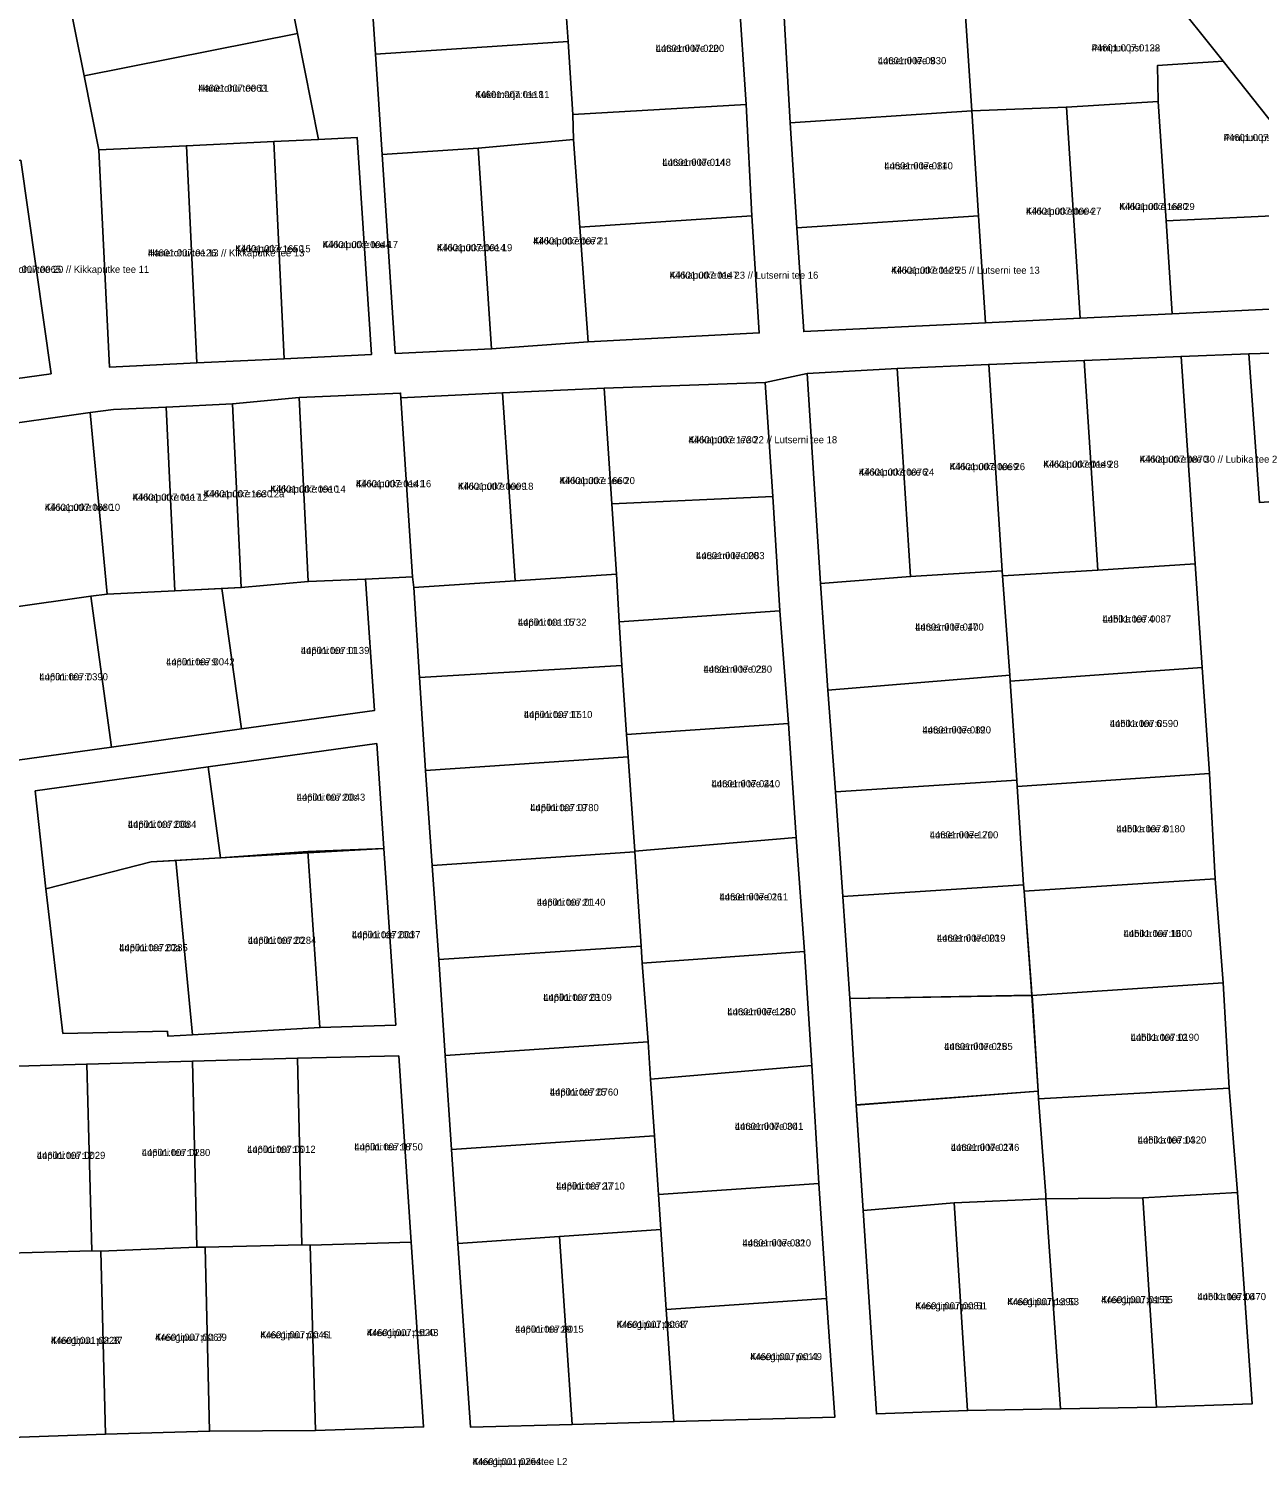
# Model space of a CAD drawing. Extents: x 551843 to 558501, y 6589003 to 6595718.
# Drawn here: x 554118.2 to 554378.5, y 6593051.3 to 6593355.7 of the extents above; entities that cross this region are included whole.
import ezdxf

# ---------------------------------------------------------------- set-up
doc = ezdxf.new("R2010")
doc.units = 0
for name, color, linetype in [('L_AADRESS', 7, 'Continuous'), ('PIIR', 7, 'Continuous'), ('TUNNUS', 7, 'Continuous')]:
    doc.layers.add(name, color=color, linetype=linetype)

msp = doc.modelspace()

# ---------------------------------------------------------------- linework, layer by layer
at = {"layer": 'PIIR'}
for points in [[(554175.06, 6593354.75), (554129.94, 6593345.76), (554126.15, 6593364.79), (554171.26, 6593373.78)], [(554191.59, 6593350.39), (554190.19, 6593371.62), (554230.91, 6593374.28), (554231.71, 6593362.02), (554232.3, 6593353.05)], [(554232.3, 6593353.05), (554231.71, 6593362.02), (554268.35, 6593364.09), (554269.98, 6593339.69), (554233.34, 6593337.62)], [(554316.4, 6593361.22), (554355.96, 6593363.33), (554359.29, 6593363.51), (554370.87, 6593348.86), (554357.01, 6593347.99), (554357.18, 6593340.35), (554337.73, 6593339.18), (554317.72, 6593338.39), (554316.26, 6593360.62)], [(554316.26, 6593360.62), (554317.72, 6593338.39), (554279.27, 6593335.87), (554278, 6593358.18)], [(554175.06, 6593354.75), (554179.53, 6593332.32), (554170.03, 6593331.87), (554151.55, 6593330.99), (554133.07, 6593330.1), (554129.94, 6593345.76)], [(554192.98, 6593329.15), (554191.59, 6593350.39), (554232.3, 6593353.05), (554233.34, 6593337.62), (554233.47, 6593332.32), (554213.29, 6593330.48)], [(554358.84, 6593315.1), (554357.18, 6593340.35), (554357.01, 6593347.99), (554370.87, 6593348.86), (554396.28, 6593316.9)], [(554269.98, 6593339.69), (554271.15, 6593316.19), (554234.81, 6593313.78), (554233.47, 6593332.32), (554233.34, 6593337.62)], [(554340.65, 6593294.5), (554320.59, 6593293.53), (554319.14, 6593316.15), (554317.72, 6593338.39), (554337.73, 6593339.18)], [(554357.18, 6593340.35), (554358.84, 6593315.1), (554360.13, 6593295.44), (554340.65, 6593294.5), (554337.73, 6593339.18)], [(554317.72, 6593338.39), (554319.14, 6593316.15), (554280.73, 6593313.59), (554279.27, 6593335.87)], [(554135.27, 6593284.15), (554133.07, 6593330.1), (554151.55, 6593330.99), (554153.75, 6593285.04)], [(554170.03, 6593331.87), (554172.23, 6593285.91), (554153.75, 6593285.04), (554151.55, 6593330.99)], [(554179.53, 6593332.32), (554187.71, 6593332.72), (554190.72, 6593286.8), (554172.23, 6593285.91), (554170.03, 6593331.87)], [(554213.29, 6593330.48), (554216.14, 6593288.01), (554195.74, 6593287.03), (554192.98, 6593329.15)], [(554213.29, 6593330.48), (554233.47, 6593332.32), (554234.81, 6593313.78), (554236.56, 6593289.51), (554216.14, 6593288.01)], [(554116.53, 6593327.97), (554122.93, 6593282.74), (554104.61, 6593280.19), (554098.21, 6593325.42)], [(554271.15, 6593316.19), (554272.75, 6593291.4), (554236.56, 6593289.51), (554234.81, 6593313.78)], [(554282.17, 6593291.65), (554280.73, 6593313.59), (554319.14, 6593316.15), (554320.59, 6593293.53)], [(554358.84, 6593315.1), (554396.28, 6593316.9), (554411.57, 6593297.9), (554360.13, 6593295.44)], [(554405.33, 6593287.82), (554407.5, 6593257.53), (554378.58, 6593255.52), (554376.33, 6593286.93)], [(554301.93, 6593283.84), (554321.32, 6593284.7), (554324.15, 6593241.06), (554304.78, 6593239.83)], [(554324.22, 6593239.97), (554324.15, 6593241.06), (554321.32, 6593284.7), (554341.49, 6593285.56), (554344.39, 6593241.21)], [(554341.49, 6593285.56), (554362.01, 6593286.41), (554364.98, 6593242.53), (554344.39, 6593241.21)], [(554301.93, 6593283.84), (554304.78, 6593239.83), (554285.73, 6593238.37), (554282.86, 6593282.78)], [(554196.86, 6593278.64), (554196.92, 6593277.68), (554199.41, 6593239.75), (554189.45, 6593239.3), (554177.34, 6593238.75), (554175.42, 6593277.75)], [(554199.69, 6593237.49), (554199.41, 6593239.75), (554196.92, 6593277.68), (554218.47, 6593278.69), (554221.13, 6593238.92)], [(554221.13, 6593238.92), (554218.47, 6593278.69), (554239.95, 6593279.66), (554241.55, 6593255.18), (554242.52, 6593240.34)], [(554239.95, 6593279.66), (554274.01, 6593280.87), (554275.63, 6593256.79), (554241.55, 6593255.18)], [(554147.25, 6593275.7), (554149.14, 6593236.81), (554134.82, 6593236.12), (554131.2, 6593274.53), (554136.13, 6593275.17)], [(554161.29, 6593276.37), (554163.18, 6593237.48), (554149.14, 6593236.81), (554147.25, 6593275.7)], [(554175.42, 6593277.75), (554177.34, 6593238.75), (554163.18, 6593237.48), (554161.29, 6593276.37)], [(554131.2, 6593274.53), (554134.82, 6593236.12), (554131.32, 6593235.64), (554114.03, 6593233.23), (554108.36, 6593271.31)], [(554277.11, 6593232.55), (554243.14, 6593230.23), (554242.52, 6593240.34), (554241.55, 6593255.18), (554275.63, 6593256.79)], [(554344.39, 6593241.21), (554364.98, 6593242.53), (554366.45, 6593220.55), (554325.84, 6593217.67), (554325.77, 6593218.95), (554324.22, 6593239.97)], [(554163.2, 6593207.57), (554159.07, 6593237.28), (554163.18, 6593237.48), (554177.34, 6593238.75), (554189.45, 6593239.3), (554191.37, 6593211.49)], [(554199.69, 6593237.49), (554221.13, 6593238.92), (554242.52, 6593240.34), (554243.14, 6593230.23), (554243.69, 6593220.98), (554200.91, 6593218.48)], [(554285.73, 6593238.37), (554304.78, 6593239.83), (554324.15, 6593241.06), (554324.22, 6593239.97), (554325.77, 6593218.95), (554287.28, 6593215.75)], [(554105.17, 6593232), (554114.03, 6593233.23), (554131.32, 6593235.64), (554135.74, 6593203.74), (554109.59, 6593200.1)], [(554134.82, 6593236.12), (554149.14, 6593236.81), (554159.07, 6593237.28), (554163.2, 6593207.57), (554135.74, 6593203.74), (554131.32, 6593235.64)], [(554277.11, 6593232.55), (554278.95, 6593208.76), (554244.66, 6593206.42), (554243.69, 6593220.98), (554243.14, 6593230.23)], [(554202.18, 6593198.78), (554200.91, 6593218.48), (554243.69, 6593220.98), (554244.66, 6593206.42), (554244.99, 6593201.65)], [(554366.45, 6593220.55), (554368.01, 6593198.12), (554327.34, 6593195.43), (554327.26, 6593196.73), (554325.84, 6593217.67)], [(554287.28, 6593215.75), (554325.77, 6593218.95), (554325.84, 6593217.67), (554327.26, 6593196.73), (554288.9, 6593194.28)], [(554278.95, 6593208.76), (554280.59, 6593184.61), (554246.44, 6593181.71), (554244.99, 6593201.65), (554244.66, 6593206.42)], [(554156.17, 6593199.53), (554119.59, 6593194.45), (554121.83, 6593173.77), (554125.45, 6593143.15), (554147.56, 6593143.6), (554147.66, 6593142.55), (554152.85, 6593142.85), (554179.81, 6593144.38), (554195.86, 6593144.9), (554193.33, 6593182.25), (554191.83, 6593204.49)], [(554191.83, 6593204.49), (554193.33, 6593182.25), (554177.3, 6593181.34), (554158.79, 6593180.27), (554156.17, 6593199.53)], [(554121.83, 6593173.77), (554119.59, 6593194.45), (554156.17, 6593199.53), (554158.79, 6593180.27), (554144.12, 6593179.43)], [(554202.18, 6593198.78), (554244.99, 6593201.65), (554246.44, 6593181.71), (554246.45, 6593181.55), (554203.57, 6593178.71)], [(554327.26, 6593196.73), (554327.34, 6593195.43), (554328.66, 6593174.57), (554290.47, 6593172.1), (554288.9, 6593194.28)], [(554368.01, 6593198.12), (554369.24, 6593175.88), (554328.79, 6593173.27), (554328.66, 6593174.57), (554327.34, 6593195.43)], [(554247.98, 6593158), (554247.78, 6593161.58), (554246.45, 6593181.55), (554246.44, 6593181.71), (554280.59, 6593184.61), (554282.36, 6593160.5)], [(554149.3, 6593179.73), (554158.79, 6593180.27), (554177.28, 6593181.62), (554179.81, 6593144.38), (554152.85, 6593142.85)], [(554193.33, 6593182.25), (554195.86, 6593144.9), (554179.81, 6593144.38), (554177.28, 6593181.62)], [(554203.57, 6593178.71), (554246.45, 6593181.55), (554247.78, 6593161.58), (554204.96, 6593158.76)], [(554121.83, 6593173.77), (554144.12, 6593179.43), (554149.3, 6593179.73), (554152.85, 6593142.85), (554147.66, 6593142.55), (554147.56, 6593143.6), (554125.45, 6593143.15)], [(554328.79, 6593173.27), (554369.24, 6593175.88), (554370.87, 6593153.82), (554330.42, 6593151.19), (554330.33, 6593152.65)], [(554328.79, 6593173.27), (554330.42, 6593151.19), (554291.89, 6593150.56), (554290.47, 6593172.1), (554328.66, 6593174.57)], [(554206.33, 6593138.47), (554204.96, 6593158.76), (554247.78, 6593161.58), (554247.98, 6593158), (554249.22, 6593141.38)], [(554282.36, 6593160.5), (554283.88, 6593136.38), (554249.76, 6593133.49), (554249.22, 6593141.38), (554247.98, 6593158)], [(554370.87, 6593153.82), (554372.19, 6593131.53), (554331.83, 6593129.31), (554331.74, 6593130.91), (554330.42, 6593151.19)], [(554291.89, 6593150.54), (554330.48, 6593151.26), (554331.74, 6593130.91), (554293.23, 6593128.04)], [(554206.33, 6593138.47), (554249.22, 6593141.38), (554249.76, 6593133.49), (554250.57, 6593121.5), (554207.67, 6593118.59)], [(554196.48, 6593138.39), (554199.12, 6593098.96), (554177.72, 6593098.34), (554175.96, 6593098.42), (554175.06, 6593137.9)], [(554130.47, 6593136.64), (554131.56, 6593097.15), (554111.31, 6593096.59), (554109.34, 6593096.54), (554108.25, 6593136.03)], [(554152.84, 6593137.24), (554153.74, 6593097.91), (554133.43, 6593097.09), (554131.56, 6593097.15), (554130.47, 6593136.64)], [(554152.84, 6593137.24), (554175.06, 6593137.9), (554175.96, 6593098.42), (554155.52, 6593097.94), (554153.74, 6593097.91)], [(554283.88, 6593136.38), (554285.34, 6593111.42), (554251.42, 6593109.09), (554250.57, 6593121.5), (554249.76, 6593133.49)], [(554293.24, 6593127.98), (554331.74, 6593130.91), (554331.83, 6593129.31), (554333.36, 6593108.94), (554333.41, 6593108.17), (554313.98, 6593107.27), (554294.73, 6593105.67)], [(554372.19, 6593131.53), (554373.91, 6593109.51), (554353.87, 6593108.34), (554333.41, 6593108.17), (554333.36, 6593108.94), (554331.83, 6593129.31)], [(554250.57, 6593121.5), (554251.42, 6593109.09), (554251.93, 6593101.62), (554230.47, 6593100.17), (554209.02, 6593098.71), (554207.67, 6593118.59)], [(554251.93, 6593101.62), (554251.42, 6593109.09), (554285.34, 6593111.42), (554287, 6593087.02), (554253.08, 6593084.7)], [(554313.98, 6593107.27), (554333.41, 6593108.17), (554336.49, 6593063.68), (554316.83, 6593063.33)], [(554333.41, 6593108.17), (554353.87, 6593108.34), (554356.76, 6593064.08), (554336.49, 6593063.68)], [(554373.91, 6593109.51), (554377.05, 6593064.78), (554356.76, 6593064.08), (554353.87, 6593108.34)], [(554294.73, 6593105.67), (554313.98, 6593107.27), (554316.83, 6593063.33), (554297.53, 6593062.63)], [(554230.47, 6593100.17), (554251.93, 6593101.62), (554253.08, 6593084.7), (554254.7, 6593061), (554233.18, 6593060.41)], [(554199.12, 6593098.96), (554201.73, 6593059.87), (554178.9, 6593059.14), (554177.72, 6593098.34)], [(554233.18, 6593060.41), (554211.67, 6593059.82), (554209.02, 6593098.71), (554230.47, 6593100.17)], [(554112.39, 6593057.6), (554111.31, 6593096.59), (554131.56, 6593097.15), (554133.43, 6593097.09), (554134.48, 6593058.36)], [(554133.43, 6593097.09), (554153.74, 6593097.91), (554155.52, 6593097.94), (554156.45, 6593058.97), (554134.48, 6593058.36)], [(554175.96, 6593098.42), (554177.72, 6593098.34), (554178.9, 6593059.14), (554156.45, 6593058.97), (554155.52, 6593097.94)], [(554287, 6593087.02), (554288.72, 6593061.93), (554254.7, 6593061), (554253.08, 6593084.7)]]:
    msp.add_lwpolyline(points, close=True, dxfattribs=at)
for points in [[(554126.15, 6593364.79), (554129.94, 6593345.76), (554133.07, 6593330.1), (554135.27, 6593284.15), (554153.75, 6593285.04), (554172.23, 6593285.91), (554190.72, 6593286.8), (554187.71, 6593332.72), (554179.53, 6593332.32), (554175.06, 6593354.75), (554171.26, 6593373.78)], [(554190.19, 6593371.62), (554191.59, 6593350.39), (554192.98, 6593329.15), (554195.74, 6593287.03), (554216.14, 6593288.01), (554236.56, 6593289.51), (554272.75, 6593291.4), (554271.15, 6593316.19), (554269.98, 6593339.69), (554268.35, 6593364.09)], [(554396.28, 6593316.9), (554370.87, 6593348.86), (554359.29, 6593363.51)], [(554278, 6593358.18), (554279.27, 6593335.87), (554280.73, 6593313.59), (554282.17, 6593291.65), (554320.59, 6593293.53), (554340.65, 6593294.5), (554360.13, 6593295.44), (554411.57, 6593297.9)], [(554104.61, 6593280.19), (554122.93, 6593282.74), (554116.53, 6593327.97)], [(554405.33, 6593287.82), (554376.33, 6593286.93), (554362.01, 6593286.41), (554341.49, 6593285.56), (554321.32, 6593284.7), (554301.93, 6593283.84), (554282.86, 6593282.78), (554274.01, 6593280.87), (554239.95, 6593279.66), (554218.47, 6593278.69), (554196.92, 6593277.68), (554196.86, 6593278.64), (554175.42, 6593277.75), (554161.29, 6593276.37), (554147.25, 6593275.7), (554136.13, 6593275.17), (554131.2, 6593274.53), (554108.36, 6593271.31)], [(554109.59, 6593200.1), (554135.74, 6593203.74), (554163.2, 6593207.57), (554191.37, 6593211.49), (554189.45, 6593239.3), (554199.41, 6593239.75), (554199.69, 6593237.49), (554200.91, 6593218.48), (554202.18, 6593198.78), (554203.57, 6593178.71), (554204.96, 6593158.76), (554206.33, 6593138.47), (554207.67, 6593118.59), (554209.02, 6593098.71), (554211.67, 6593059.82), (554233.18, 6593060.41), (554254.7, 6593061), (554288.72, 6593061.93), (554287, 6593087.02), (554285.34, 6593111.42), (554283.88, 6593136.38), (554282.36, 6593160.5), (554280.59, 6593184.61), (554278.95, 6593208.76), (554277.11, 6593232.55), (554275.63, 6593256.79), (554274.01, 6593280.87), (554282.86, 6593282.78), (554285.73, 6593238.37), (554287.28, 6593215.75), (554288.9, 6593194.28), (554290.47, 6593172.1), (554291.89, 6593150.56), (554293.23, 6593128.04), (554294.73, 6593105.67), (554297.53, 6593062.63), (554316.83, 6593063.33), (554336.49, 6593063.68), (554356.76, 6593064.08), (554377.05, 6593064.78), (554373.91, 6593109.51), (554372.19, 6593131.53), (554370.87, 6593153.82), (554369.24, 6593175.88), (554368.01, 6593198.12), (554366.45, 6593220.55), (554364.98, 6593242.53), (554362.01, 6593286.41), (554376.33, 6593286.93), (554378.58, 6593255.52)], [(554112.39, 6593057.6), (554134.48, 6593058.36), (554156.45, 6593058.97), (554178.9, 6593059.14), (554201.73, 6593059.87), (554199.12, 6593098.96), (554196.48, 6593138.39), (554175.06, 6593137.9), (554152.84, 6593137.24), (554130.47, 6593136.64), (554108.25, 6593136.03)]]:
    msp.add_lwpolyline(points, dxfattribs=at)

# ---------------------------------------------------------------- texts
at = {"layer": 'L_AADRESS'}
for s, p in [('Lutserni tee 12', (554250.84, 6593350.86)), ('Pirnipuu pst 128', (554343.06, 6593350.95)), ('Lutserni tee 9', (554297.82, 6593348.25)), ('Hanerohu tee 11', (554154.06, 6593342.43)), ('Kukemarja tee 11', (554212.65, 6593341.1)), ('Pirnipuu pst 130', (554371.01, 6593331.98)), ('Lutserni tee 14', (554252.25, 6593326.74)), ('Lutserni tee 11', (554299.21, 6593325.99)), ('Kikkaputke tee 27', (554329.18, 6593316.39)), ('Kikkaputke tee 29', (554348.93, 6593317.38)), ('Kikkaputke tee 21', (554224.93, 6593310.1)), ('Hanerohu tee 13 // Kikkaputke tee 13', (554143.41, 6593307.57)), ('Kikkaputke tee 15', (554161.89, 6593308.45)), ('Kikkaputke tee 17', (554180.38, 6593309.33)), ('Kikkaputke tee 19', (554204.56, 6593308.68)), ('Hanerohu tee 20 // Kikkaputke tee 11', (554110.57, 6593304.08)), ('Kikkaputke tee 23 // Lutserni tee 16', (554253.8, 6593302.85)), ('Kikkaputke tee 25 // Lutserni tee 13', (554300.65, 6593303.9)), ('Kikkaputke tee 22 // Lutserni tee 18', (554257.79, 6593268.03)), ('Kikkaputke tee 26', (554313.04, 6593262.34)), ('Kikkaputke tee 28', (554332.86, 6593262.85)), ('Kikkaputke tee 30 // Lubika tee 2', (554353.23, 6593263.91)), ('Kikkaputke tee 16', (554187.41, 6593258.73)), ('Kikkaputke tee 20', (554230.5, 6593259.39)), ('Kikkaputke tee 24', (554293.82, 6593261.19)), ('Kikkaputke tee 12', (554140.17, 6593255.87)), ('Kikkaputke tee 12a', (554155.21, 6593256.59)), ('Kikkaputke tee 14', (554169.32, 6593257.59)), ('Kikkaputke tee 18', (554209.03, 6593258.18)), ('Kikkaputke tee 10', (554121.59, 6593253.73)), ('Lutserni tee 20', (554259.38, 6593243.51)), ('Lupiini tee 15', (554221.7, 6593229.41)), ('Lutserni tee 17', (554305.74, 6593228.4)), ('Lubika tee 4', (554345.38, 6593230.1)), ('Lupiini tee 11', (554175.77, 6593223.44)), ('Lupiini tee 9', (554147.26, 6593221.03)), ('Lutserni tee 22', (554260.96, 6593219.49)), ('Lupiini tee 7', (554120.46, 6593217.87)), ('Lupiini tee 17', (554222.95, 6593209.88)), ('Lutserni tee 19', (554307.28, 6593206.62)), ('Lubika tee 6', (554346.91, 6593207.99)), ('Lutserni tee 24', (554262.66, 6593195.24)), ('Lupiini tee 20c', (554174.89, 6593192.38)), ('Lupiini tee 19', (554224.3, 6593190.18)), ('Lupiini tee 20b', (554139.18, 6593186.65)), ('Lubika tee 8', (554348.33, 6593185.7)), ('Lutserni tee 21', (554308.82, 6593184.42)), ('Lupiini tee 21', (554225.69, 6593170.16)), ('Lutserni tee 26', (554264.35, 6593171.3)), ('Lupiini tee 20', (554164.55, 6593162.1)), ('Lupiini tee 20d', (554186.57, 6593163.29)), ('Lutserni tee 23', (554310.34, 6593162.57)), ('Lubika tee 10', (554349.83, 6593163.54)), ('Lupiini tee 20a', (554137.34, 6593160.55)), ('Lupiini tee 23', (554227.06, 6593150.02)), ('Lutserni tee 28', (554266.01, 6593146.99)), ('Lutserni tee 25', (554311.87, 6593139.65)), ('Lubika tee 12', (554351.32, 6593141.57)), ('Lupiini tee 25', (554228.45, 6593129.99)), ('Lutserni tee 30', (554267.58, 6593122.74)), ('Lupiini tee 18', (554187.09, 6593118.39)), ('Lutserni tee 27', (554313.27, 6593118.29)), ('Lubika tee 14', (554352.82, 6593119.85)), ('Lupiini tee 12', (554119.91, 6593116.59)), ('Lupiini tee 14', (554142.11, 6593117.2)), ('Lupiini tee 16', (554164.4, 6593117.87)), ('Lupiini tee 27', (554229.8, 6593110.11)), ('Lutserni tee 32', (554269.21, 6593098.06)), ('Kreegipuu pst 53', (554325.23, 6593085.64)), ('Kreegipuu pst 55', (554345.08, 6593086.06)), ('Lubika tee 16', (554365.46, 6593086.7)), ('Kreegipuu pst 51', (554305.78, 6593084.76)), ('Kreegipuu pst 43', (554189.72, 6593079.09)), ('Lupiini tee 29', (554221.1, 6593079.81)), ('Kreegipuu pst 47', (554242.59, 6593080.83)), ('Kreegipuu pst 37', (554122.89, 6593077.44)), ('Kreegipuu pst 39', (554144.94, 6593078.1)), ('Kreegipuu pst 41', (554167.21, 6593078.63)), ('Kreegipuu pst 49', (554270.85, 6593074.01)), ('Kreegipuu puiestee L2', (554212.09, 6593051.8))]:
    msp.add_text(s, height=1.5, dxfattribs=at).set_placement(p)
at = {"layer": 'TUNNUS'}
for s, p in [('44601:007:0200', (554250.84, 6593350.86)), ('44601:007:0132', (554343.06, 6593350.95)), ('44601:007:0830', (554297.82, 6593348.25)), ('44601:007:0063', (554154.06, 6593342.43)), ('44601:007:0118', (554212.65, 6593341.1)), ('44601:007:0124', (554371.01, 6593331.98)), ('44601:007:0148', (554252.25, 6593326.74)), ('44601:007:0840', (554299.21, 6593325.99)), ('44601:007:0004', (554329.18, 6593316.39)), ('44601:007:1680', (554348.93, 6593317.38)), ('44601:007:0072', (554224.93, 6593310.1)), ('44601:007:0126', (554143.41, 6593307.57)), ('44601:007:1650', (554161.89, 6593308.45)), ('44601:007:0044', (554180.38, 6593309.33)), ('44601:007:0014', (554204.56, 6593308.68)), ('44601:007:0065', (554110.57, 6593304.08)), ('44601:007:0147', (554253.8, 6593302.85)), ('44601:007:0125', (554300.65, 6593303.9)), ('44601:007:1730', (554257.79, 6593268.03)), ('44601:007:0069', (554313.04, 6593262.34)), ('44601:007:0149', (554332.86, 6593262.85)), ('44601:007:0870', (554353.23, 6593263.91)), ('44601:007:0141', (554187.41, 6593258.73)), ('44601:007:1660', (554230.5, 6593259.39)), ('44601:007:0076', (554293.82, 6593261.19)), ('44601:007:0117', (554140.17, 6593255.87)), ('44601:007:1630', (554155.21, 6593256.59)), ('44601:007:0910', (554169.32, 6593257.59)), ('44601:007:0009', (554209.03, 6593258.18)), ('44601:007:0880', (554121.59, 6593253.73)), ('44601:007:0083', (554259.38, 6593243.51)), ('44601:001:0732', (554221.7, 6593229.41)), ('44601:007:0400', (554305.74, 6593228.4)), ('44601:007:0087', (554345.38, 6593230.1)), ('44601:007:0139', (554175.77, 6593223.44)), ('44601:007:0042', (554147.26, 6593221.03)), ('44601:007:0250', (554260.96, 6593219.49)), ('44601:007:0390', (554120.46, 6593217.87)), ('44601:007:1510', (554222.95, 6593209.88)), ('44601:007:0820', (554307.28, 6593206.62)), ('44601:007:0590', (554346.91, 6593207.99)), ('44601:007:0410', (554262.66, 6593195.24)), ('44601:007:0043', (554174.89, 6593192.38)), ('44601:007:0780', (554224.3, 6593190.18)), ('44601:007:0084', (554139.18, 6593186.65)), ('44601:007:0180', (554348.33, 6593185.7)), ('44601:007:1700', (554308.82, 6593184.42)), ('44601:007:0140', (554225.69, 6593170.16)), ('44601:007:0111', (554264.35, 6593171.3)), ('44601:007:0284', (554164.55, 6593162.1)), ('44601:007:0037', (554186.57, 6593163.29)), ('44601:007:0019', (554310.34, 6593162.57)), ('44601:007:1600', (554349.83, 6593163.54)), ('44601:007:0285', (554137.34, 6593160.55)), ('44601:007:0109', (554227.06, 6593150.02)), ('44601:007:1260', (554266.01, 6593146.99)), ('44601:007:0185', (554311.87, 6593139.65)), ('44601:007:0190', (554351.32, 6593141.57)), ('44601:007:0760', (554228.45, 6593129.99)), ('44601:007:0041', (554267.58, 6593122.74)), ('44601:007:0750', (554187.09, 6593118.39)), ('44601:007:0320', (554352.82, 6593119.85)), ('44601:007:0029', (554119.91, 6593116.59)), ('44601:007:0280', (554142.11, 6593117.2)), ('44601:007:0012', (554164.4, 6593117.87)), ('44601:007:0146', (554313.27, 6593118.29)), ('44601:007:1710', (554229.8, 6593110.11)), ('44601:007:0810', (554269.21, 6593098.06)), ('44601:007:1390', (554325.23, 6593085.64)), ('44601:007:0151', (554345.08, 6593086.06)), ('44601:007:0470', (554365.46, 6593086.7)), ('44601:007:0081', (554305.78, 6593084.76)), ('44601:007:1520', (554189.72, 6593079.09)), ('44601:007:0015', (554221.1, 6593079.81)), ('44601:007:0068', (554242.59, 6593080.83)), ('44601:001:0328', (554122.89, 6593077.44)), ('44601:007:0067', (554144.94, 6593078.1)), ('44601:007:0045', (554167.21, 6593078.63)), ('44601:007:0011', (554270.85, 6593074.01)), ('44601:001:0264', (554212.09, 6593051.8))]:
    msp.add_text(s, height=1.5, dxfattribs=at).set_placement(p)

doc.saveas('drawing.dxf')
